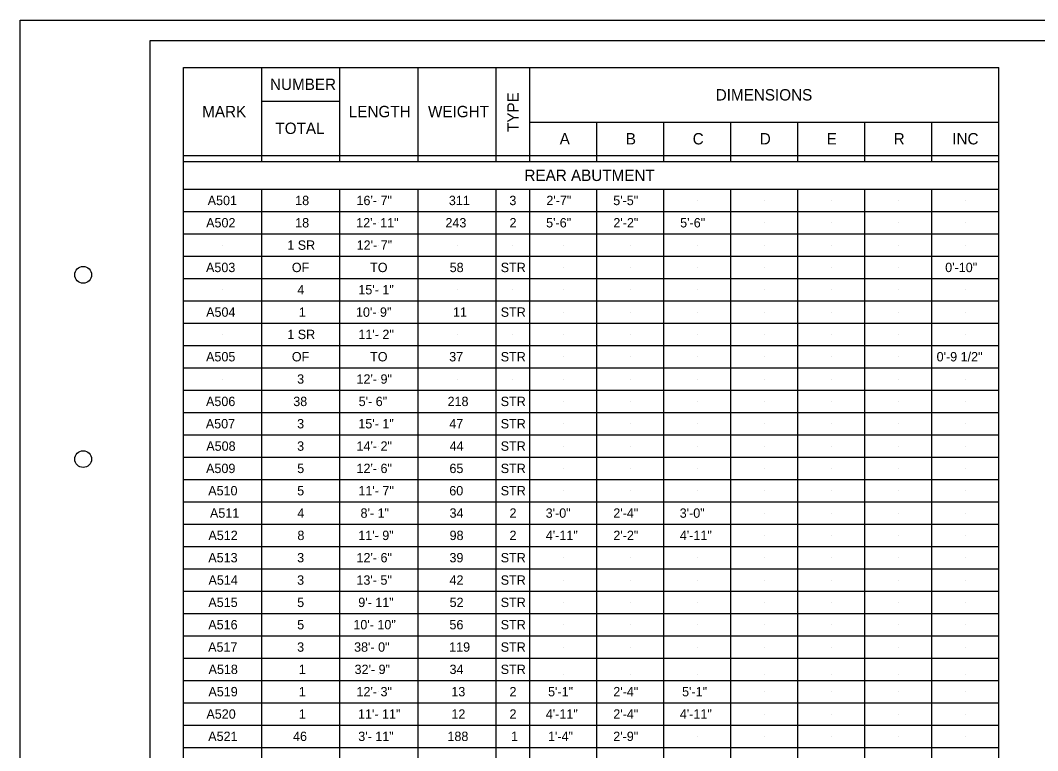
# Model space of a CAD drawing. Extents: x -9.2 to 26.7, y -0.9 to 21.1.
# Drawn here: x -7.9 to 7.28, y 10.01 to 20.91 of the extents above; entities that cross this region are included whole.
import ezdxf

# ---------------------------------------------------------------- set-up
doc = ezdxf.new("R2010")
doc.units = 0
for name, color, linetype in [('BR_P_Gen_Text', 7, 'Continuous'), ('SC_Scratch1', 7, 'Continuous'), ('SH_Border', 7, 'Continuous'), ('SH_Cut_Line', 7, 'Continuous'), ('TX_P_1', 7, 'Continuous')]:
    doc.layers.add(name, color=color, linetype=linetype)

msp = doc.modelspace()

# ---------------------------------------------------------------- linework, layer by layer
at = {"layer": 'BR_P_Gen_Text'}
for p, q in [((-5.469, 20.207), (6.697, 20.207)), ((-5.469, 3.39), (-5.469, 20.207)), ((-4.302, 18.806), (-4.302, 20.207)), ((-3.135, 18.806), (-3.135, 20.207)), ((-1.969, 18.806), (-1.969, 20.207)), ((-0.802, 18.806), (-0.802, 20.207)), ((-0.302, 18.806), (-0.302, 20.207)), ((6.697, 3.39), (6.697, 20.207)), ((-4.302, 19.707), (-3.135, 19.707)), ((-0.302, 19.394), (6.697, 19.394)), ((0.698, 18.806), (0.698, 19.394)), ((1.698, 18.806), (1.698, 19.394)), ((2.698, 18.806), (2.698, 19.394)), ((3.698, 18.806), (3.698, 19.394)), ((4.698, 18.806), (4.698, 19.394)), ((5.697, 18.806), (5.698, 19.394)), ((-5.469, 18.894), (6.697, 18.894)), ((-5.469, 18.806), (6.697, 18.806)), ((-5.469, 18.39), (6.697, 18.39)), ((-5.469, 18.39), (6.697, 18.39)), ((-4.302, 3.723), (-4.302, 18.39)), ((-3.135, 3.723), (-3.135, 18.39)), ((-1.969, 3.39), (-1.969, 18.39)), ((-0.802, 3.39), (-0.802, 18.39)), ((-0.302, 3.723), (-0.302, 18.39)), ((0.698, 3.723), (0.698, 18.39)), ((1.698, 3.723), (1.698, 18.39)), ((2.698, 3.723), (2.698, 18.39)), ((3.698, 3.723), (3.698, 18.39)), ((4.698, 3.723), (4.698, 18.39)), ((5.698, 3.723), (5.698, 18.39)), ((-5.469, 18.056), (6.697, 18.056)), ((-5.469, 17.723), (6.697, 17.723)), ((-5.469, 17.39), (6.697, 17.39)), ((-5.469, 17.056), (6.697, 17.056)), ((-5.469, 16.723), (6.697, 16.723)), ((-5.469, 16.39), (6.697, 16.39)), ((-5.469, 16.056), (6.697, 16.057)), ((-5.469, 15.723), (6.697, 15.723)), ((-5.469, 15.39), (6.697, 15.39)), ((-5.469, 15.056), (6.697, 15.056)), ((-5.469, 14.723), (6.697, 14.723)), ((-5.469, 14.39), (6.697, 14.39)), ((-5.469, 14.056), (6.697, 14.056)), ((-5.469, 13.723), (6.697, 13.723)), ((-5.469, 13.39), (6.697, 13.39)), ((-5.469, 13.056), (6.697, 13.056)), ((-5.469, 12.723), (6.697, 12.723)), ((-5.469, 12.39), (6.697, 12.39)), ((-5.469, 12.056), (6.697, 12.056)), ((-5.469, 11.723), (6.697, 11.723)), ((-5.469, 11.39), (6.697, 11.39)), ((-5.469, 11.056), (6.697, 11.056)), ((-5.469, 10.723), (6.697, 10.723)), ((-5.469, 10.39), (6.697, 10.39)), ((-5.469, 10.056), (6.697, 10.056))]:
    msp.add_line(p, q, dxfattribs=at)
at = {"layer": 'SC_Scratch1'}
for p, q in [((-4.885, 18.223), (-4.885, 18.223)), ((-3.719, 18.223), (-3.719, 18.223)), ((-2.552, 18.223), (-2.552, 18.223)), ((-1.385, 18.223), (-1.385, 18.223)), ((-1.385, 18.223), (-1.385, 18.223)), ((-0.552, 18.223), (-0.552, 18.223)), ((0.198, 18.223), (0.198, 18.223)), ((1.198, 18.223), (1.198, 18.223)), ((2.198, 18.223), (2.198, 18.223)), ((3.198, 18.223), (3.198, 18.223)), ((4.198, 18.223), (4.198, 18.223)), ((5.197, 18.223), (5.197, 18.223)), ((6.197, 18.223), (6.197, 18.223)), ((6.197, 18.223), (6.197, 18.223)), ((-4.885, 17.89), (-4.885, 17.89)), ((-3.719, 17.89), (-3.719, 17.89)), ((-2.552, 17.89), (-2.552, 17.89)), ((-1.385, 17.89), (-1.385, 17.89)), ((-1.385, 17.89), (-1.385, 17.89)), ((-0.552, 17.89), (-0.552, 17.89)), ((0.198, 17.89), (0.198, 17.89)), ((1.198, 17.89), (1.198, 17.89)), ((2.198, 17.89), (2.198, 17.89)), ((3.198, 17.89), (3.198, 17.89)), ((4.198, 17.89), (4.198, 17.89)), ((5.198, 17.89), (5.198, 17.89)), ((6.197, 17.89), (6.197, 17.89)), ((6.197, 17.89), (6.197, 17.89)), ((-4.885, 17.556), (-4.885, 17.556)), ((-3.719, 17.556), (-3.719, 17.556)), ((-2.552, 17.556), (-2.552, 17.556)), ((-1.385, 17.556), (-1.385, 17.556)), ((-1.385, 17.556), (-1.385, 17.556)), ((-0.552, 17.556), (-0.552, 17.556)), ((0.198, 17.556), (0.198, 17.556)), ((1.198, 17.556), (1.198, 17.556)), ((2.198, 17.556), (2.198, 17.556)), ((3.198, 17.556), (3.198, 17.556)), ((4.198, 17.556), (4.198, 17.556)), ((5.198, 17.556), (5.198, 17.556)), ((6.197, 17.556), (6.197, 17.556)), ((6.197, 17.556), (6.197, 17.556)), ((-4.885, 17.223), (-4.885, 17.223)), ((-3.719, 17.223), (-3.719, 17.223)), ((-2.552, 17.223), (-2.552, 17.223)), ((-1.385, 17.223), (-1.385, 17.223)), ((-1.385, 17.223), (-1.385, 17.223)), ((-0.552, 17.223), (-0.552, 17.223)), ((0.198, 17.223), (0.198, 17.223)), ((1.198, 17.223), (1.198, 17.223)), ((2.198, 17.223), (2.198, 17.223)), ((3.198, 17.223), (3.198, 17.223)), ((4.198, 17.223), (4.198, 17.223)), ((5.197, 17.223), (5.197, 17.223)), ((6.197, 17.223), (6.197, 17.223)), ((6.197, 17.223), (6.197, 17.223)), ((-4.885, 16.89), (-4.885, 16.89)), ((-3.719, 16.89), (-3.719, 16.89)), ((-2.552, 16.89), (-2.552, 16.89)), ((-1.385, 16.89), (-1.385, 16.89)), ((-1.385, 16.89), (-1.385, 16.89)), ((-0.552, 16.89), (-0.552, 16.89)), ((0.198, 16.89), (0.198, 16.89)), ((1.198, 16.89), (1.198, 16.89)), ((2.198, 16.89), (2.198, 16.89)), ((3.198, 16.89), (3.198, 16.89)), ((4.198, 16.89), (4.198, 16.89)), ((5.197, 16.89), (5.197, 16.89)), ((6.197, 16.89), (6.197, 16.89)), ((6.197, 16.89), (6.197, 16.89)), ((-4.885, 16.556), (-4.885, 16.556)), ((-3.719, 16.556), (-3.719, 16.556)), ((-2.552, 16.556), (-2.552, 16.556)), ((-1.385, 16.556), (-1.385, 16.556)), ((-1.385, 16.556), (-1.385, 16.556)), ((-0.552, 16.556), (-0.552, 16.556)), ((0.198, 16.556), (0.198, 16.556)), ((1.198, 16.556), (1.198, 16.556)), ((2.198, 16.556), (2.198, 16.556)), ((3.198, 16.556), (3.198, 16.556)), ((4.198, 16.556), (4.198, 16.556)), ((5.197, 16.556), (5.197, 16.556)), ((6.197, 16.556), (6.197, 16.556)), ((6.197, 16.556), (6.197, 16.556)), ((-4.885, 16.223), (-4.885, 16.223)), ((-3.719, 16.223), (-3.719, 16.223)), ((-2.552, 16.223), (-2.552, 16.223)), ((-1.385, 16.223), (-1.385, 16.223)), ((-1.385, 16.223), (-1.385, 16.223)), ((-0.552, 16.223), (-0.552, 16.223)), ((0.198, 16.223), (0.198, 16.223)), ((1.198, 16.223), (1.198, 16.223)), ((2.198, 16.223), (2.198, 16.223)), ((3.198, 16.223), (3.198, 16.223)), ((4.198, 16.223), (4.198, 16.223)), ((5.197, 16.223), (5.197, 16.223)), ((6.197, 16.223), (6.197, 16.223)), ((6.197, 16.223), (6.197, 16.223)), ((-4.885, 15.89), (-4.885, 15.89)), ((-3.719, 15.89), (-3.719, 15.89)), ((-2.552, 15.89), (-2.552, 15.89)), ((-1.385, 15.89), (-1.385, 15.89)), ((-1.385, 15.89), (-1.385, 15.89)), ((-0.552, 15.89), (-0.552, 15.89)), ((0.198, 15.89), (0.198, 15.89)), ((1.198, 15.89), (1.198, 15.89)), ((2.198, 15.89), (2.198, 15.89)), ((3.198, 15.89), (3.198, 15.89)), ((4.198, 15.89), (4.198, 15.89)), ((5.197, 15.89), (5.197, 15.89)), ((6.198, 15.89), (6.198, 15.89)), ((6.198, 15.89), (6.198, 15.89)), ((-4.885, 15.556), (-4.885, 15.556)), ((-3.719, 15.556), (-3.719, 15.556)), ((-2.552, 15.556), (-2.552, 15.556)), ((-1.385, 15.556), (-1.385, 15.556)), ((-1.385, 15.556), (-1.385, 15.556)), ((-0.552, 15.556), (-0.552, 15.556)), ((0.198, 15.556), (0.198, 15.556)), ((1.198, 15.556), (1.198, 15.556)), ((2.198, 15.556), (2.198, 15.556)), ((3.198, 15.556), (3.198, 15.556)), ((4.198, 15.556), (4.198, 15.556)), ((5.197, 15.556), (5.197, 15.556)), ((6.198, 15.556), (6.198, 15.556)), ((6.198, 15.556), (6.198, 15.556)), ((-4.885, 15.223), (-4.885, 15.223)), ((-3.719, 15.223), (-3.719, 15.223)), ((-2.552, 15.223), (-2.552, 15.223)), ((-1.385, 15.223), (-1.385, 15.223)), ((-1.385, 15.223), (-1.385, 15.223)), ((-0.552, 15.223), (-0.552, 15.223)), ((0.198, 15.223), (0.198, 15.223)), ((1.198, 15.223), (1.198, 15.223)), ((2.198, 15.223), (2.198, 15.223)), ((3.198, 15.223), (3.198, 15.223)), ((4.198, 15.223), (4.198, 15.223)), ((5.197, 15.223), (5.197, 15.223)), ((6.197, 15.223), (6.197, 15.223)), ((6.197, 15.223), (6.197, 15.223)), ((-4.885, 14.89), (-4.885, 14.89)), ((-3.719, 14.89), (-3.719, 14.89)), ((-2.552, 14.89), (-2.552, 14.89)), ((-1.385, 14.89), (-1.385, 14.89)), ((-1.385, 14.89), (-1.385, 14.89)), ((-0.552, 14.89), (-0.552, 14.89)), ((0.198, 14.89), (0.198, 14.89)), ((1.198, 14.89), (1.198, 14.89)), ((2.198, 14.89), (2.198, 14.89)), ((3.198, 14.89), (3.198, 14.89)), ((4.198, 14.89), (4.198, 14.89)), ((5.198, 14.89), (5.198, 14.89)), ((6.197, 14.89), (6.197, 14.89)), ((6.197, 14.89), (6.197, 14.89)), ((-4.885, 14.556), (-4.885, 14.556)), ((-3.719, 14.556), (-3.719, 14.556)), ((-2.552, 14.556), (-2.552, 14.556)), ((-1.385, 14.556), (-1.385, 14.556)), ((-1.385, 14.556), (-1.385, 14.556)), ((-0.552, 14.556), (-0.552, 14.556)), ((0.198, 14.556), (0.198, 14.556)), ((1.198, 14.556), (1.198, 14.556)), ((2.198, 14.556), (2.198, 14.556)), ((3.198, 14.556), (3.198, 14.556)), ((4.198, 14.556), (4.198, 14.556)), ((5.197, 14.556), (5.197, 14.556)), ((6.197, 14.556), (6.197, 14.556)), ((6.197, 14.556), (6.197, 14.556)), ((-4.885, 14.223), (-4.885, 14.223)), ((-3.719, 14.223), (-3.719, 14.223)), ((-2.552, 14.223), (-2.552, 14.223)), ((-1.385, 14.223), (-1.385, 14.223)), ((-1.385, 14.223), (-1.385, 14.223)), ((-0.552, 14.223), (-0.552, 14.223)), ((0.198, 14.223), (0.198, 14.223)), ((1.198, 14.223), (1.198, 14.223)), ((2.198, 14.223), (2.198, 14.223)), ((3.198, 14.223), (3.198, 14.223)), ((4.198, 14.223), (4.198, 14.223)), ((5.197, 14.223), (5.197, 14.223)), ((6.197, 14.223), (6.197, 14.223)), ((6.197, 14.223), (6.197, 14.223)), ((-4.885, 13.89), (-4.885, 13.89)), ((-3.719, 13.89), (-3.719, 13.89)), ((-2.552, 13.89), (-2.552, 13.89)), ((-1.385, 13.89), (-1.385, 13.89)), ((-1.385, 13.89), (-1.385, 13.89)), ((-0.552, 13.89), (-0.552, 13.89)), ((0.198, 13.89), (0.198, 13.89)), ((1.198, 13.89), (1.198, 13.89)), ((2.198, 13.89), (2.198, 13.89)), ((3.198, 13.89), (3.198, 13.89)), ((4.198, 13.89), (4.198, 13.89)), ((5.197, 13.89), (5.197, 13.89)), ((6.197, 13.89), (6.197, 13.89)), ((6.197, 13.89), (6.197, 13.89)), ((-4.885, 13.556), (-4.885, 13.556)), ((-3.719, 13.556), (-3.719, 13.556)), ((-2.552, 13.556), (-2.552, 13.556)), ((-1.385, 13.556), (-1.385, 13.556)), ((-1.385, 13.556), (-1.385, 13.556)), ((-0.552, 13.556), (-0.552, 13.556)), ((0.198, 13.556), (0.198, 13.556)), ((1.198, 13.556), (1.198, 13.556)), ((2.198, 13.556), (2.198, 13.556)), ((3.198, 13.556), (3.198, 13.556)), ((4.198, 13.556), (4.198, 13.556)), ((5.197, 13.556), (5.197, 13.556)), ((6.197, 13.556), (6.197, 13.556)), ((6.197, 13.556), (6.197, 13.556)), ((-4.885, 13.223), (-4.885, 13.223)), ((-3.719, 13.223), (-3.719, 13.223)), ((-2.552, 13.223), (-2.552, 13.223)), ((-1.385, 13.223), (-1.385, 13.223)), ((-1.385, 13.223), (-1.385, 13.223)), ((-0.552, 13.223), (-0.552, 13.223)), ((0.198, 13.223), (0.198, 13.223)), ((1.198, 13.223), (1.198, 13.223)), ((2.198, 13.223), (2.198, 13.223)), ((3.198, 13.223), (3.198, 13.223)), ((4.198, 13.223), (4.198, 13.223)), ((5.198, 13.223), (5.198, 13.223)), ((6.198, 13.223), (6.198, 13.223)), ((6.198, 13.223), (6.198, 13.223)), ((-4.885, 12.89), (-4.885, 12.89)), ((-3.719, 12.89), (-3.719, 12.89)), ((-2.552, 12.89), (-2.552, 12.89)), ((-1.385, 12.89), (-1.385, 12.89)), ((-1.385, 12.89), (-1.385, 12.89)), ((-0.552, 12.89), (-0.552, 12.89)), ((0.198, 12.89), (0.198, 12.89)), ((1.198, 12.89), (1.198, 12.89)), ((2.198, 12.89), (2.198, 12.89)), ((3.198, 12.89), (3.198, 12.89)), ((4.198, 12.89), (4.198, 12.89)), ((5.198, 12.89), (5.198, 12.89)), ((6.198, 12.89), (6.198, 12.89)), ((6.198, 12.89), (6.198, 12.89)), ((-4.885, 12.556), (-4.885, 12.556)), ((-3.719, 12.556), (-3.719, 12.556)), ((-2.552, 12.556), (-2.552, 12.556)), ((-2.552, 12.556), (-2.552, 12.556)), ((-1.385, 12.556), (-1.385, 12.556)), ((-1.385, 12.556), (-1.385, 12.556)), ((-0.552, 12.556), (-0.552, 12.556)), ((-0.552, 12.556), (-0.552, 12.556)), ((0.198, 12.556), (0.198, 12.556)), ((0.198, 12.556), (0.198, 12.556)), ((1.198, 12.556), (1.198, 12.556)), ((1.198, 12.556), (1.198, 12.556)), ((2.198, 12.556), (2.198, 12.556)), ((2.198, 12.556), (2.198, 12.556)), ((3.198, 12.556), (3.198, 12.556)), ((4.198, 12.556), (4.198, 12.556)), ((5.198, 12.556), (5.198, 12.556)), ((6.197, 12.556), (6.197, 12.556)), ((6.197, 12.556), (6.197, 12.556)), ((-4.885, 12.223), (-4.885, 12.223)), ((-3.719, 12.223), (-3.719, 12.223)), ((-2.552, 12.223), (-2.552, 12.223)), ((-1.385, 12.223), (-1.385, 12.223)), ((-1.385, 12.223), (-1.385, 12.223)), ((-0.552, 12.223), (-0.552, 12.223)), ((0.198, 12.223), (0.198, 12.223)), ((1.198, 12.223), (1.198, 12.223)), ((2.198, 12.223), (2.198, 12.223)), ((3.198, 12.223), (3.198, 12.223)), ((4.198, 12.223), (4.198, 12.223)), ((5.198, 12.223), (5.198, 12.223)), ((6.197, 12.223), (6.197, 12.223)), ((6.197, 12.223), (6.197, 12.223)), ((-4.885, 11.89), (-4.885, 11.89)), ((-3.719, 11.89), (-3.719, 11.89)), ((-2.552, 11.89), (-2.552, 11.89)), ((-1.385, 11.89), (-1.385, 11.89)), ((-1.385, 11.89), (-1.385, 11.89)), ((-0.552, 11.89), (-0.552, 11.89)), ((0.198, 11.89), (0.198, 11.89)), ((1.198, 11.89), (1.198, 11.89)), ((2.198, 11.89), (2.198, 11.89)), ((3.198, 11.89), (3.198, 11.89)), ((4.198, 11.89), (4.198, 11.89)), ((5.197, 11.89), (5.197, 11.89)), ((6.197, 11.89), (6.197, 11.89)), ((6.197, 11.89), (6.197, 11.89)), ((-4.885, 11.556), (-4.885, 11.556)), ((-3.719, 11.556), (-3.719, 11.556)), ((-2.552, 11.556), (-2.552, 11.556)), ((-1.385, 11.556), (-1.385, 11.556)), ((-1.385, 11.556), (-1.385, 11.556)), ((-0.552, 11.556), (-0.552, 11.556)), ((0.198, 11.556), (0.198, 11.556)), ((1.198, 11.556), (1.198, 11.556)), ((2.198, 11.556), (2.198, 11.556)), ((3.198, 11.556), (3.198, 11.556)), ((4.198, 11.556), (4.198, 11.556)), ((5.197, 11.556), (5.197, 11.556)), ((6.198, 11.556), (6.198, 11.556)), ((6.198, 11.556), (6.198, 11.556)), ((2.698, 11.305), (2.698, 11.322)), ((3.698, 11.305), (3.698, 11.322)), ((-4.885, 11.139), (-4.885, 11.139)), ((-3.719, 11.139), (-3.719, 11.139)), ((-2.552, 11.139), (-2.552, 11.139)), ((-1.385, 11.139), (-1.385, 11.139)), ((-1.385, 11.139), (-1.385, 11.139)), ((-0.552, 11.139), (-0.552, 11.139)), ((0.198, 11.139), (0.198, 11.139)), ((1.198, 11.139), (1.198, 11.139)), ((2.198, 11.139), (2.198, 11.139)), ((3.198, 11.139), (3.198, 11.139)), ((4.198, 11.139), (4.198, 11.139)), ((5.197, 11.139), (5.197, 11.139)), ((6.197, 11.139), (6.197, 11.139)), ((6.197, 11.139), (6.197, 11.139)), ((-4.885, 10.89), (-4.885, 10.89)), ((-3.719, 10.89), (-3.719, 10.89)), ((-2.552, 10.89), (-2.552, 10.89)), ((-1.385, 10.89), (-1.385, 10.89)), ((-1.385, 10.89), (-1.385, 10.89)), ((-0.552, 10.89), (-0.552, 10.89)), ((0.198, 10.89), (0.198, 10.89)), ((1.198, 10.89), (1.198, 10.89)), ((2.198, 10.89), (2.198, 10.89)), ((3.198, 10.89), (3.198, 10.89)), ((4.198, 10.89), (4.198, 10.89)), ((5.197, 10.89), (5.197, 10.89)), ((6.198, 10.89), (6.198, 10.89)), ((6.198, 10.89), (6.198, 10.89)), ((-4.885, 10.556), (-4.885, 10.556)), ((-3.719, 10.556), (-3.719, 10.556)), ((-2.552, 10.556), (-2.552, 10.556)), ((-1.385, 10.556), (-1.385, 10.556)), ((-1.385, 10.556), (-1.385, 10.556)), ((-0.552, 10.556), (-0.552, 10.556)), ((0.198, 10.556), (0.198, 10.556)), ((1.198, 10.556), (1.198, 10.556)), ((2.198, 10.556), (2.198, 10.556)), ((3.198, 10.556), (3.198, 10.556)), ((4.198, 10.556), (4.198, 10.556)), ((5.197, 10.556), (5.197, 10.556)), ((6.198, 10.556), (6.198, 10.556)), ((6.198, 10.556), (6.198, 10.556)), ((-4.885, 10.223), (-4.885, 10.223)), ((-3.719, 10.223), (-3.719, 10.223)), ((-2.552, 10.223), (-2.552, 10.223)), ((-1.385, 10.223), (-1.385, 10.223)), ((-1.385, 10.223), (-1.385, 10.223)), ((-0.552, 10.223), (-0.552, 10.223)), ((0.198, 10.223), (0.198, 10.223)), ((1.198, 10.223), (1.198, 10.223)), ((2.198, 10.223), (2.198, 10.223)), ((3.198, 10.223), (3.198, 10.223)), ((4.198, 10.223), (4.198, 10.223)), ((5.198, 10.223), (5.198, 10.223)), ((6.197, 10.223), (6.197, 10.223)), ((6.197, 10.223), (6.197, 10.223))]:
    msp.add_line(p, q, dxfattribs=at)
at = {"layer": 'SH_Border'}
msp.add_lwpolyline([(-5.966, 20.612), (25.534, 20.612), (25.534, -0.388), (-5.966, -0.388)], close=True, dxfattribs=at)
for centre in [(-6.966, 17.112), (-6.966, 14.362)]:
    msp.add_circle(centre, 0.125, dxfattribs=at)
at = {"layer": 'SH_Cut_Line'}
msp.add_lwpolyline([(26.096, -0.738), (-7.904, -0.738), (-7.904, 20.912), (26.096, 20.912)], close=True, dxfattribs=at)
at = {"layer": 'TX_P_1'}
msp.add_line((0.614, 18.598), (0.614, 18.598), dxfattribs=at)

# ---------------------------------------------------------------- texts
at = {"layer": 'BR_P_Gen_Text'}
for s, p in [('A501', (-5.108, 18.153)), ('18', (-3.802, 18.153)), (' 16\'- 7"', (-2.939, 18.153)), ('311', (-1.509, 18.153)), ('3', (-0.606, 18.153)), ('2\'-7"', (-0.054, 18.153)), ('5\'-5"', (0.944, 18.153)), ('A502', (-5.131, 17.82)), ('18', (-3.802, 17.82)), (' 12\'- 11"', (-2.944, 17.82)), ('243', (-1.56, 17.82)), ('2', (-0.604, 17.82)), ('5\'-6"', (-0.057, 17.82)), ('2\'-2"', (0.946, 17.82)), ('5\'-6"', (1.943, 17.82)), ('1 SR', (-3.92, 17.486)), (' 12\'- 7"', (-2.937, 17.486)), ('A503', (-5.133, 17.153)), ('OF', (-3.852, 17.153)), ('TO', (-2.684, 17.153)), ('58', (-1.497, 17.153)), ('STR', (-0.735, 17.153)), ('0\'-10"', (5.898, 17.153)), ('4', (-3.77, 16.82)), (' 15\'- 1"', (-2.912, 16.82)), ('A504', (-5.131, 16.486)), ('1', (-3.748, 16.486)), (' 10\'- 9"', (-2.947, 16.486)), ('11', (-1.447, 16.486)), ('STR', (-0.735, 16.486)), ('1 SR', (-3.92, 16.153)), (' 11\'- 2"', (-2.911, 16.153)), ('A505', (-5.132, 15.82)), ('OF', (-3.852, 15.82)), ('TO', (-2.684, 15.82)), ('37', (-1.504, 15.82)), ('STR', (-0.735, 15.82)), ('0\'-9 1/2"', (5.77, 15.82)), ('3', (-3.773, 15.487)), (' 12\'- 9"', (-2.939, 15.487)), ('A506', (-5.133, 15.153)), ('38', (-3.831, 15.153)), (' 5\'- 6"', (-2.907, 15.153)), ('218', (-1.528, 15.153)), ('STR', (-0.735, 15.153)), ('A507', (-5.136, 14.82)), ('3', (-3.773, 14.82)), (' 15\'- 1"', (-2.912, 14.82)), ('47', (-1.503, 14.82)), ('STR', (-0.735, 14.82)), ('A508', (-5.129, 14.486)), ('3', (-3.773, 14.486)), (' 14\'- 2"', (-2.939, 14.486)), ('44', (-1.498, 14.486)), ('STR', (-0.735, 14.486)), ('A509', (-5.132, 14.153)), ('5', (-3.772, 14.153)), (' 12\'- 6"', (-2.939, 14.153)), ('65', (-1.5, 14.153)), ('STR', (-0.735, 14.153)), ('A510', (-5.1, 13.82)), ('5', (-3.772, 13.82)), (' 11\'- 7"', (-2.911, 13.82)), ('60', (-1.503, 13.82)), ('STR', (-0.735, 13.82)), ('A511', (-5.074, 13.486)), ('4', (-3.77, 13.486)), (' 8\'- 1"', (-2.879, 13.486)), ('34', (-1.499, 13.486)), ('2', (-0.604, 13.486)), ('3\'-0"', (-0.064, 13.486)), ('2\'-4"', (0.945, 13.486)), ('3\'-0"', (1.936, 13.486)), ('A512', (-5.097, 13.153)), ('8', (-3.769, 13.153)), (' 11\'- 9"', (-2.913, 13.153)), ('98', (-1.498, 13.153)), ('2', (-0.604, 13.153)), ('4\'-11"', (-0.062, 13.153)), ('2\'-2"', (0.946, 13.153)), ('4\'-11"', (1.938, 13.153)), ('A513', (-5.099, 12.82)), ('3', (-3.773, 12.82)), (' 12\'- 6"', (-2.939, 12.82)), ('39', (-1.5, 12.82)), ('STR', (-0.735, 12.82)), ('A514', (-5.096, 12.486)), ('3', (-3.773, 12.486)), (' 13\'- 5"', (-2.94, 12.486)), ('42', (-1.499, 12.486)), ('STR', (-0.735, 12.486)), ('A515', (-5.098, 12.153)), ('5', (-3.772, 12.153)), (' 9\'- 11"', (-2.913, 12.153)), ('52', (-1.498, 12.153)), ('STR', (-0.735, 12.153)), ('A516', (-5.099, 11.82)), ('5', (-3.772, 11.82)), (' 10\'- 10"', (-2.986, 11.82)), ('56', (-1.5, 11.82)), ('STR', (-0.735, 11.82)), ('A517', (-5.101, 11.486)), ('3', (-3.773, 11.486)), (' 38\'- 0"', (-2.975, 11.486)), ('119', (-1.504, 11.486)), ('STR', (-0.735, 11.486)), ('A518', (-5.095, 11.153)), ('1', (-3.748, 11.153)), (' 32\'- 9"', (-2.968, 11.153)), ('34', (-1.499, 11.153)), ('STR', (-0.735, 11.153)), ('A519', (-5.097, 10.82)), ('1', (-3.748, 10.82)), (' 12\'- 3"', (-2.939, 10.82)), ('13', (-1.472, 10.82)), ('2', (-0.604, 10.82)), ('5\'-1"', (-0.028, 10.82)), ('2\'-4"', (0.945, 10.82)), ('5\'-1"', (1.972, 10.82)), ('A520', (-5.127, 10.486)), ('12', (-1.471, 10.486)), ('2', (-0.604, 10.486)), ('2\'-4"', (0.945, 10.486)), ('1', (-3.748, 10.486)), (' 11\'- 11"', (-2.917, 10.486)), ('4\'-11"', (-0.062, 10.486)), ('4\'-11"', (1.938, 10.486)), ('A521', (-5.1, 10.153)), ('46', (-3.834, 10.153)), (' 3\'- 11"', (-2.913, 10.153)), ('188', (-1.53, 10.153)), ('1', (-0.581, 10.153)), ('1\'-4"', (-0.029, 10.153)), ('2\'-9"', (0.944, 10.153))]:
    msp.add_text(s, height=0.14, dxfattribs=at).set_placement(p)
at = {"layer": 'TX_P_1'}
for s, rotation, p in [('NUMBER', 0.0002, (-4.178, 19.872)), ('TYPE', 90.0002, (-0.467, 19.245)), ('DIMENSIONS', 0.0002, (2.474, 19.715)), ('MARK', 0.0002, (-5.19, 19.465)), ('LENGTH', 0.0002, (-3.002, 19.465)), ('WEIGHT', 0.0002, (-1.82, 19.465)), ('TOTAL', 0.0002, (-4.097, 19.215)), ('A', 0.0002, (0.145, 19.059)), ('B', 0.0002, (1.132, 19.059)), ('C', 0.0002, (2.13, 19.059)), ('D', 0.0002, (3.131, 19.059)), ('E', 0.0002, (4.129, 19.059)), ('R', 0.0002, (5.129, 19.059)), ('INC', 0.0002, (6.004, 19.059)), ('REAR ABUTMENT', 0.0002, (-0.381, 18.513))]:
    msp.add_text(s, height=0.17, rotation=rotation, dxfattribs=at).set_placement(p)

doc.saveas('drawing.dxf')
